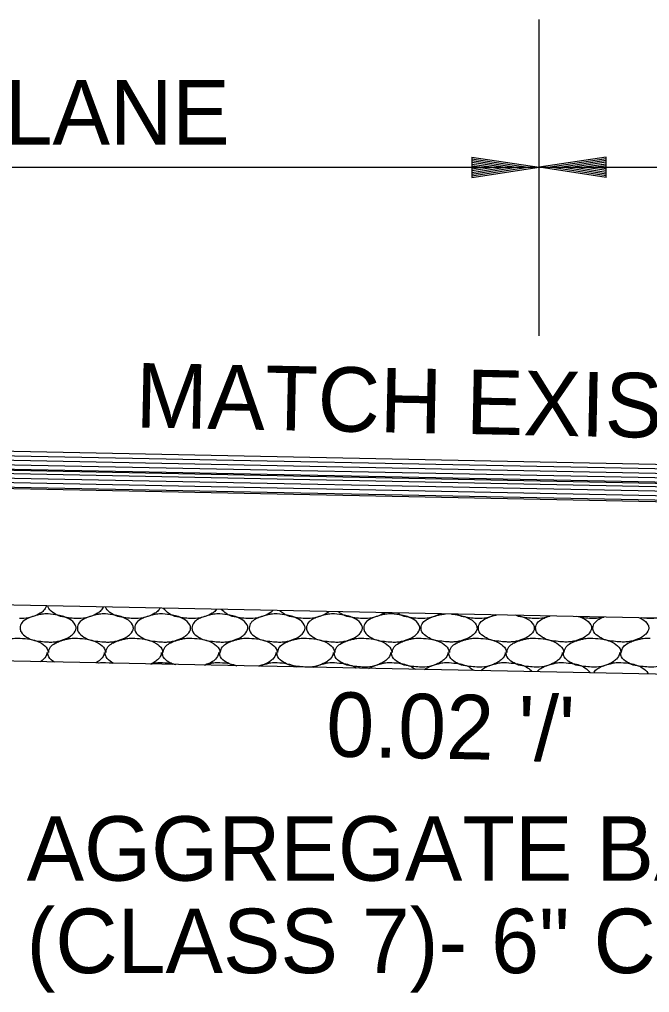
# Model space of a CAD drawing. Extents: x 1364961 to 1365294, y 367927 to 368034.
# Drawn here: x 1365200.85 to 1365206.49, y 367967.68 to 367976.38 of the extents above; entities that cross this region are included whole.
import ezdxf

# ---------------------------------------------------------------- set-up
doc = ezdxf.new("R2010")
doc.units = 0
doc.layers.add('Default', color=7, linetype='Continuous')

msp = doc.modelspace()

# ---------------------------------------------------------------- linework, layer by layer
at = {"layer": 'Default'}
for p, q in [((1365205.4981, 367973.5514), (1365205.4981, 367976.3797)), ((1365204.8981, 367975.1485), (1365205.4981, 367975.0585)), ((1365204.8981, 367975.1485), (1365204.8981, 367974.9685)), ((1365204.8981, 367975.1335), (1365205.3981, 367975.0585)), ((1365204.8981, 367975.1185), (1365205.2951, 367975.0585)), ((1365204.8981, 367975.1035), (1365205.1951, 367975.0585)), ((1365204.8981, 367975.0875), (1365205.0931, 367975.0585)), ((1365204.8981, 367975.0725), (1365204.9931, 367975.0585)), ((1365206.0981, 367975.1485), (1365205.4981, 367975.0585)), ((1365206.0981, 367975.1335), (1365205.5981, 367975.0585)), ((1365206.0981, 367975.1185), (1365205.7011, 367975.0585)), ((1365206.0981, 367975.1035), (1365205.8011, 367975.0585)), ((1365206.0981, 367975.0875), (1365205.9031, 367975.0585)), ((1365206.0981, 367975.0725), (1365206.0031, 367975.0585)), ((1365206.0981, 367974.9685), (1365206.0981, 367975.1485)), ((1365193.4981, 367975.0585), (1365205.4981, 367975.0585)), ((1365204.8981, 367974.9685), (1365205.4981, 367975.0585)), ((1365204.8981, 367975.0295), (1365205.0931, 367975.0585)), ((1365204.8981, 367974.9985), (1365205.2951, 367975.0585)), ((1365204.8981, 367974.9835), (1365205.3981, 367975.0585)), ((1365204.8981, 367975.0135), (1365205.1951, 367975.0585)), ((1365204.8981, 367975.0445), (1365204.9931, 367975.0585)), ((1365205.4981, 367975.0585), (1365217.487, 367975.0585)), ((1365206.0981, 367974.9685), (1365205.4981, 367975.0585)), ((1365206.0981, 367974.9835), (1365205.5981, 367975.0585)), ((1365206.0981, 367974.9985), (1365205.7011, 367975.0585)), ((1365206.0981, 367975.0135), (1365205.8011, 367975.0585)), ((1365206.0981, 367975.0295), (1365205.9031, 367975.0585)), ((1365206.0981, 367975.0445), (1365206.0031, 367975.0585)), ((1365229.476, 367971.9458), (1365193.4981, 367972.6644)), ((1365229.476, 367971.9058), (1365193.4991, 367972.6244)), ((1365229.476, 367971.8657), (1365193.4991, 367972.5844)), ((1365229.476, 367971.7758), (1365193.2513, 367972.4993)), ((1365229.476, 367971.8257), (1365193.5011, 367972.5444)), ((1365229.476, 367971.7857), (1365193.5011, 367972.5044)), ((1365229.476, 367971.7456), (1365193.5021, 367972.4644)), ((1365229.476, 367971.7056), (1365193.5031, 367972.4244)), ((1365229.476, 367971.6656), (1365193.5031, 367972.3844)), ((1365229.476, 367971.6126), (1365193.4981, 367972.3314)), ((1365229.476, 367971.6256), (1365193.5051, 367972.3444)), ((1365217.479, 367970.8114), (1365193.4921, 367971.2914)), ((1365200.8541, 367970.8514), (1365200.8601, 367970.8514)), ((1365201.3661, 367970.8514), (1365201.3721, 367970.8514)), ((1365201.8781, 367970.8514), (1365201.8841, 367970.8514)), ((1365202.3901, 367970.8514), (1365202.3961, 367970.8514)), ((1365202.9021, 367970.8514), (1365202.9081, 367970.8514)), ((1365203.4141, 367970.8514), (1365203.4201, 367970.8514)), ((1365203.9261, 367970.8514), (1365203.9321, 367970.8514)), ((1365204.4381, 367970.8514), (1365204.4441, 367970.8514)), ((1365204.9501, 367970.8514), (1365204.9561, 367970.8514)), ((1365205.4621, 367970.8514), (1365205.4681, 367970.8514)), ((1365205.9741, 367970.8514), (1365205.9801, 367970.8514)), ((1365206.4861, 367970.8514), (1365206.4921, 367970.8514)), ((1365217.479, 367970.3114), (1365193.4821, 367970.7914)), ((1365201.6221, 367970.6334), (1365201.6901, 367970.6274))]:
    msp.add_line(p, q, dxfattribs=at)
for points in [[(1365201.0961, 367971.1394), (1365201.0701, 367971.0974), (1365201.0401, 367971.0734), (1365200.9781, 367971.0454), (1365200.8921, 367971.0274), (1365200.8541, 367971.0274)], [(1365201.3661, 367971.0274), (1365201.3581, 367971.0274), (1365201.2921, 367971.0334), (1365201.2201, 367971.0454), (1365201.1661, 367971.0714), (1365201.1161, 367971.1174), (1365201.1091, 367971.1394)], [(1365201.6041, 367971.1294), (1365201.5821, 367971.0974), (1365201.5521, 367971.0734), (1365201.4901, 367971.0454), (1365201.4041, 367971.0274), (1365201.3661, 367971.0274)], [(1365201.8781, 367971.0274), (1365201.8701, 367971.0274), (1365201.8041, 367971.0334), (1365201.7321, 367971.0454), (1365201.6781, 367971.0714), (1365201.6281, 367971.1174), (1365201.6231, 367971.1284)], [(1365202.1111, 367971.1194), (1365202.0941, 367971.0974), (1365202.0641, 367971.0734), (1365202.0021, 367971.0454), (1365201.9161, 367971.0274), (1365201.8781, 367971.0274)], [(1365202.3901, 367971.0274), (1365202.3821, 367971.0274), (1365202.3161, 367971.0334), (1365202.2441, 367971.0454), (1365202.1901, 367971.0714), (1365202.1401, 367971.1174), (1365202.1391, 367971.1184)], [(1365202.6161, 367971.1084), (1365202.6061, 367971.0974), (1365202.5761, 367971.0734), (1365202.5141, 367971.0454), (1365202.4281, 367971.0274), (1365202.3901, 367971.0274)], [(1365202.9021, 367971.0274), (1365202.8941, 367971.0274), (1365202.8281, 367971.0334), (1365202.7561, 367971.0454), (1365202.7021, 367971.0714), (1365202.6581, 367971.1084)], [(1365203.1191, 367971.0984), (1365203.1181, 367971.0974), (1365203.0881, 367971.0734), (1365203.0261, 367971.0454), (1365202.9401, 367971.0274), (1365202.9021, 367971.0274)], [(1365203.4141, 367971.0274), (1365203.4061, 367971.0274), (1365203.3401, 367971.0334), (1365203.2681, 367971.0454), (1365203.2141, 367971.0714), (1365203.1791, 367971.0974)], [(1365203.6211, 367971.0884), (1365203.6001, 367971.0734), (1365203.5381, 367971.0454), (1365203.4521, 367971.0274), (1365203.4141, 367971.0274)], [(1365203.9261, 367971.0274), (1365203.9181, 367971.0274), (1365203.8521, 367971.0334), (1365203.7801, 367971.0454), (1365203.7261, 367971.0714), (1365203.7031, 367971.0874)], [(1365204.1211, 367971.0784), (1365204.1121, 367971.0734), (1365204.0501, 367971.0454), (1365203.9641, 367971.0274), (1365203.9261, 367971.0274)], [(1365204.4381, 367971.0274), (1365204.4301, 367971.0274), (1365204.3641, 367971.0334), (1365204.2921, 367971.0454), (1365204.2381, 367971.0714), (1365204.2301, 367971.0764)], [(1365201.1101, 367971.0674), (1365201.1981, 367971.0574), (1365201.3001, 367971.0214), (1365201.3521, 367970.9714), (1365201.3601, 367970.9414), (1365201.3321, 367970.8874), (1365201.3021, 367970.8634), (1365201.2401, 367970.8354), (1365201.1541, 367970.8174), (1365201.1101, 367970.8174), (1365201.0441, 367970.8234), (1365200.9721, 367970.8354), (1365200.9181, 367970.8614), (1365200.8681, 367970.9074), (1365200.8601, 367970.9414), (1365200.8761, 367970.9894), (1365200.9161, 367971.0214), (1365200.9561, 367971.0394), (1365201.0161, 367971.0574), (1365201.0541, 367971.0654), (1365201.1101, 367971.0674)], [(1365201.6221, 367971.0674), (1365201.7101, 367971.0574), (1365201.8121, 367971.0214), (1365201.8641, 367970.9714), (1365201.8721, 367970.9414), (1365201.8441, 367970.8874), (1365201.8141, 367970.8634), (1365201.7521, 367970.8354), (1365201.6661, 367970.8174), (1365201.6221, 367970.8174), (1365201.5561, 367970.8234), (1365201.4841, 367970.8354), (1365201.4301, 367970.8614), (1365201.3801, 367970.9074), (1365201.3721, 367970.9414), (1365201.3881, 367970.9894), (1365201.4281, 367971.0214), (1365201.4681, 367971.0394), (1365201.5281, 367971.0574), (1365201.5661, 367971.0654), (1365201.6221, 367971.0674)], [(1365202.1341, 367971.0674), (1365202.2221, 367971.0574), (1365202.3241, 367971.0214), (1365202.3761, 367970.9714), (1365202.3841, 367970.9414), (1365202.3561, 367970.8874), (1365202.3261, 367970.8634), (1365202.2641, 367970.8354), (1365202.1781, 367970.8174), (1365202.1341, 367970.8174), (1365202.0681, 367970.8234), (1365201.9961, 367970.8354), (1365201.9421, 367970.8614), (1365201.8921, 367970.9074), (1365201.8841, 367970.9414), (1365201.9001, 367970.9894), (1365201.9401, 367971.0214), (1365201.9801, 367971.0394), (1365202.0401, 367971.0574), (1365202.0781, 367971.0654), (1365202.1341, 367971.0674)], [(1365202.6461, 367971.0674), (1365202.7341, 367971.0574), (1365202.8361, 367971.0214), (1365202.8881, 367970.9714), (1365202.8961, 367970.9414), (1365202.8681, 367970.8874), (1365202.8381, 367970.8634), (1365202.7761, 367970.8354), (1365202.6901, 367970.8174), (1365202.6461, 367970.8174), (1365202.5801, 367970.8234), (1365202.5081, 367970.8354), (1365202.4541, 367970.8614), (1365202.4041, 367970.9074), (1365202.3961, 367970.9414), (1365202.4121, 367970.9894), (1365202.4521, 367971.0214), (1365202.4921, 367971.0394), (1365202.5521, 367971.0574), (1365202.5901, 367971.0654), (1365202.6461, 367971.0674)], [(1365203.1581, 367971.0674), (1365203.2461, 367971.0574), (1365203.3481, 367971.0214), (1365203.4001, 367970.9714), (1365203.4081, 367970.9414), (1365203.3801, 367970.8874), (1365203.3501, 367970.8634), (1365203.2881, 367970.8354), (1365203.2021, 367970.8174), (1365203.1581, 367970.8174), (1365203.0921, 367970.8234), (1365203.0201, 367970.8354), (1365202.9661, 367970.8614), (1365202.9161, 367970.9074), (1365202.9081, 367970.9414), (1365202.9241, 367970.9894), (1365202.9641, 367971.0214), (1365203.0041, 367971.0394), (1365203.0641, 367971.0574), (1365203.1021, 367971.0654), (1365203.1581, 367971.0674)], [(1365203.6701, 367971.0674), (1365203.7581, 367971.0574), (1365203.8601, 367971.0214), (1365203.9121, 367970.9714), (1365203.9201, 367970.9414), (1365203.8921, 367970.8874), (1365203.8621, 367970.8634), (1365203.8001, 367970.8354), (1365203.7141, 367970.8174), (1365203.6701, 367970.8174), (1365203.6041, 367970.8234), (1365203.5321, 367970.8354), (1365203.4781, 367970.8614), (1365203.4281, 367970.9074), (1365203.4201, 367970.9414), (1365203.4361, 367970.9894), (1365203.4761, 367971.0214), (1365203.5161, 367971.0394), (1365203.5761, 367971.0574), (1365203.6141, 367971.0654), (1365203.6701, 367971.0674)], [(1365204.1821, 367971.0674), (1365204.2701, 367971.0574), (1365204.3721, 367971.0214), (1365204.4241, 367970.9714), (1365204.4321, 367970.9414), (1365204.4041, 367970.8874), (1365204.3741, 367970.8634), (1365204.3121, 367970.8354), (1365204.2261, 367970.8174), (1365204.1821, 367970.8174), (1365204.1161, 367970.8234), (1365204.0441, 367970.8354), (1365203.9901, 367970.8614), (1365203.9401, 367970.9074), (1365203.9321, 367970.9414), (1365203.9481, 367970.9894), (1365203.9881, 367971.0214), (1365204.0281, 367971.0394), (1365204.0881, 367971.0574), (1365204.1261, 367971.0654), (1365204.1821, 367971.0674)], [(1365204.6161, 367971.0684), (1365204.5621, 367971.0454), (1365204.4761, 367971.0274), (1365204.4381, 367971.0274)], [(1365204.7171, 367971.0664), (1365204.7821, 367971.0574), (1365204.8841, 367971.0214), (1365204.9361, 367970.9714), (1365204.9441, 367970.9414), (1365204.9161, 367970.8874), (1365204.8861, 367970.8634), (1365204.8241, 367970.8354), (1365204.7381, 367970.8174), (1365204.6941, 367970.8174), (1365204.6281, 367970.8234), (1365204.5561, 367970.8354), (1365204.5021, 367970.8614), (1365204.4521, 367970.9074), (1365204.4441, 367970.9414), (1365204.4601, 367970.9894), (1365204.5001, 367971.0214), (1365204.5401, 367971.0394), (1365204.6001, 367971.0574), (1365204.6381, 367971.0654), (1365204.6621, 367971.0674)], [(1365204.9501, 367971.0274), (1365204.9421, 367971.0274), (1365204.8761, 367971.0334), (1365204.8041, 367971.0454), (1365204.7591, 367971.0664)], [(1365205.1081, 367971.0594), (1365205.0741, 367971.0454), (1365204.9881, 367971.0274), (1365204.9501, 367971.0274)], [(1365205.3051, 367971.0554), (1365205.3961, 367971.0214), (1365205.4481, 367970.9714), (1365205.4561, 367970.9414), (1365205.4281, 367970.8874), (1365205.3981, 367970.8634), (1365205.3361, 367970.8354), (1365205.2501, 367970.8174), (1365205.2061, 367970.8174), (1365205.1401, 367970.8234), (1365205.0681, 367970.8354), (1365205.0141, 367970.8614), (1365204.9641, 367970.9074), (1365204.9561, 367970.9414), (1365204.9721, 367970.9894), (1365205.0121, 367971.0214), (1365205.0521, 367971.0394), (1365205.1121, 367971.0574), (1365205.1171, 367971.0584)], [(1365205.4621, 367971.0274), (1365205.4541, 367971.0274), (1365205.3881, 367971.0334), (1365205.3161, 367971.0454), (1365205.2901, 367971.0554)], [(1365205.5971, 367971.0494), (1365205.5861, 367971.0454), (1365205.5001, 367971.0274), (1365205.4621, 367971.0274)], [(1365205.8561, 367971.0444), (1365205.9081, 367971.0214), (1365205.9601, 367970.9714), (1365205.9681, 367970.9414), (1365205.9401, 367970.8874), (1365205.9101, 367970.8634), (1365205.8481, 367970.8354), (1365205.7621, 367970.8174), (1365205.7181, 367970.8174), (1365205.6521, 367970.8234), (1365205.5801, 367970.8354), (1365205.5261, 367970.8614), (1365205.4761, 367970.9074), (1365205.4681, 367970.9414), (1365205.4841, 367970.9894), (1365205.5241, 367971.0214), (1365205.5641, 367971.0394), (1365205.5951, 367971.0494)], [(1365205.9741, 367971.0274), (1365205.9661, 367971.0274), (1365205.9001, 367971.0334), (1365205.8321, 367971.0444)], [(1365206.0791, 367971.0394), (1365206.0121, 367971.0274), (1365205.9741, 367971.0274)], [(1365206.3961, 367971.0334), (1365206.4201, 367971.0214), (1365206.4721, 367970.9714), (1365206.4801, 367970.9414), (1365206.4521, 367970.8874), (1365206.4221, 367970.8634), (1365206.3601, 367970.8354), (1365206.2741, 367970.8174), (1365206.2301, 367970.8174), (1365206.1641, 367970.8234), (1365206.0921, 367970.8354), (1365206.0381, 367970.8614), (1365205.9881, 367970.9074), (1365205.9801, 367970.9414), (1365205.9961, 367970.9894), (1365206.0361, 367971.0214), (1365206.0761, 367971.0394), (1365206.0771, 367971.0394)], [(1365206.4861, 367971.0274), (1365206.4781, 367971.0274), (1365206.4181, 367971.0324)], [(1365206.5501, 367971.0304), (1365206.5241, 367971.0274), (1365206.4861, 367971.0274)], [(1365200.6041, 367970.7234), (1365200.6041, 367970.7254), (1365200.6201, 367970.7734), (1365200.6601, 367970.8054), (1365200.7001, 367970.8234), (1365200.7601, 367970.8414), (1365200.7981, 367970.8494), (1365200.8541, 367970.8514)], [(1365200.8601, 367970.8514), (1365200.9481, 367970.8414), (1365201.0501, 367970.8054), (1365201.1021, 367970.7554), (1365201.1101, 367970.7254), (1365201.1101, 367970.7234)], [(1365201.1161, 367970.7234), (1365201.1161, 367970.7254), (1365201.1321, 367970.7734), (1365201.1721, 367970.8054), (1365201.2121, 367970.8234), (1365201.2721, 367970.8414), (1365201.3101, 367970.8494), (1365201.3661, 367970.8514)], [(1365201.3721, 367970.8514), (1365201.4601, 367970.8414), (1365201.5621, 367970.8054), (1365201.6141, 367970.7554), (1365201.6221, 367970.7254), (1365201.6221, 367970.7234)], [(1365201.6281, 367970.7234), (1365201.6281, 367970.7254), (1365201.6441, 367970.7734), (1365201.6841, 367970.8054), (1365201.7241, 367970.8234), (1365201.7841, 367970.8414), (1365201.8221, 367970.8494), (1365201.8781, 367970.8514)], [(1365201.8841, 367970.8514), (1365201.9721, 367970.8414), (1365202.0741, 367970.8054), (1365202.1261, 367970.7554), (1365202.1341, 367970.7254), (1365202.1341, 367970.7234)], [(1365202.1401, 367970.7234), (1365202.1401, 367970.7254), (1365202.1561, 367970.7734), (1365202.1961, 367970.8054), (1365202.2361, 367970.8234), (1365202.2961, 367970.8414), (1365202.3341, 367970.8494), (1365202.3901, 367970.8514)], [(1365202.3961, 367970.8514), (1365202.4841, 367970.8414), (1365202.5861, 367970.8054), (1365202.6381, 367970.7554), (1365202.6461, 367970.7254), (1365202.6461, 367970.7234)], [(1365202.6521, 367970.7234), (1365202.6521, 367970.7254), (1365202.6681, 367970.7734), (1365202.7081, 367970.8054), (1365202.7481, 367970.8234), (1365202.8081, 367970.8414), (1365202.8461, 367970.8494), (1365202.9021, 367970.8514)], [(1365202.9081, 367970.8514), (1365202.9961, 367970.8414), (1365203.0981, 367970.8054), (1365203.1501, 367970.7554), (1365203.1581, 367970.7254), (1365203.1581, 367970.7234)], [(1365203.1641, 367970.7234), (1365203.1641, 367970.7254), (1365203.1801, 367970.7734), (1365203.2201, 367970.8054), (1365203.2601, 367970.8234), (1365203.3201, 367970.8414), (1365203.3581, 367970.8494), (1365203.4141, 367970.8514)], [(1365203.4201, 367970.8514), (1365203.5081, 367970.8414), (1365203.6101, 367970.8054), (1365203.6621, 367970.7554), (1365203.6701, 367970.7254), (1365203.6701, 367970.7234)], [(1365203.6761, 367970.7234), (1365203.6761, 367970.7254), (1365203.6921, 367970.7734), (1365203.7321, 367970.8054), (1365203.7721, 367970.8234), (1365203.8321, 367970.8414), (1365203.8701, 367970.8494), (1365203.9261, 367970.8514)], [(1365203.9321, 367970.8514), (1365204.0201, 367970.8414), (1365204.1221, 367970.8054), (1365204.1741, 367970.7554), (1365204.1821, 367970.7254), (1365204.1821, 367970.7234)], [(1365204.1881, 367970.7234), (1365204.1881, 367970.7254), (1365204.2041, 367970.7734), (1365204.2441, 367970.8054), (1365204.2841, 367970.8234), (1365204.3441, 367970.8414), (1365204.3821, 367970.8494), (1365204.4381, 367970.8514)], [(1365204.4441, 367970.8514), (1365204.5321, 367970.8414), (1365204.6341, 367970.8054), (1365204.6861, 367970.7554), (1365204.6941, 367970.7254), (1365204.6941, 367970.7234)], [(1365204.7001, 367970.7234), (1365204.7001, 367970.7254), (1365204.7161, 367970.7734), (1365204.7561, 367970.8054), (1365204.7961, 367970.8234), (1365204.8561, 367970.8414), (1365204.8941, 367970.8494), (1365204.9501, 367970.8514)], [(1365204.9561, 367970.8514), (1365205.0441, 367970.8414), (1365205.1461, 367970.8054), (1365205.1981, 367970.7554), (1365205.2061, 367970.7254), (1365205.2061, 367970.7234)], [(1365205.2121, 367970.7234), (1365205.2121, 367970.7254), (1365205.2281, 367970.7734), (1365205.2681, 367970.8054), (1365205.3081, 367970.8234), (1365205.3681, 367970.8414), (1365205.4061, 367970.8494), (1365205.4621, 367970.8514)], [(1365205.4681, 367970.8514), (1365205.5561, 367970.8414), (1365205.6581, 367970.8054), (1365205.7101, 367970.7554), (1365205.7181, 367970.7254), (1365205.7181, 367970.7234)], [(1365205.7241, 367970.7234), (1365205.7241, 367970.7254), (1365205.7401, 367970.7734), (1365205.7801, 367970.8054), (1365205.8201, 367970.8234), (1365205.8801, 367970.8414), (1365205.9181, 367970.8494), (1365205.9741, 367970.8514)], [(1365205.9801, 367970.8514), (1365206.0681, 367970.8414), (1365206.1701, 367970.8054), (1365206.2221, 367970.7554), (1365206.2301, 367970.7254), (1365206.2301, 367970.7234)], [(1365206.2361, 367970.7234), (1365206.2361, 367970.7254), (1365206.2521, 367970.7734), (1365206.2921, 367970.8054), (1365206.3321, 367970.8234), (1365206.3921, 367970.8414), (1365206.4301, 367970.8494), (1365206.4861, 367970.8514)], [(1365201.0981, 367970.7234), (1365201.0981, 367970.7174), (1365201.0701, 367970.6634), (1365201.0411, 367970.6404)], [(1365201.1661, 367970.6374), (1365201.1161, 367970.6834), (1365201.1081, 367970.7174), (1365201.1081, 367970.7234)], [(1365201.6101, 367970.7234), (1365201.6101, 367970.7174), (1365201.5821, 367970.6634), (1365201.5521, 367970.6394), (1365201.5351, 367970.6304)], [(1365201.6951, 367970.6274), (1365201.6781, 367970.6374), (1365201.6281, 367970.6834), (1365201.6201, 367970.7174), (1365201.6201, 367970.7234)], [(1365202.1221, 367970.7234), (1365202.1221, 367970.7174), (1365202.0941, 367970.6634), (1365202.0641, 367970.6394), (1365202.0261, 367970.6204)], [(1365202.2281, 367970.6164), (1365202.1901, 367970.6374), (1365202.1401, 367970.6834), (1365202.1321, 367970.7174), (1365202.1321, 367970.7234)], [(1365202.6341, 367970.7234), (1365202.6341, 367970.7174), (1365202.6061, 367970.6634), (1365202.5761, 367970.6394), (1365202.5141, 367970.6114), (1365202.5121, 367970.6104)], [(1365202.7861, 367970.6054), (1365202.7561, 367970.6114), (1365202.7021, 367970.6374), (1365202.6521, 367970.6834), (1365202.6441, 367970.7174), (1365202.6441, 367970.7234)], [(1365203.1461, 367970.7234), (1365203.1461, 367970.7174), (1365203.1181, 367970.6634), (1365203.0881, 367970.6394), (1365203.0261, 367970.6114), (1365202.9911, 367970.6014)], [(1365203.4141, 367970.5934), (1365203.4061, 367970.5934), (1365203.3401, 367970.5994), (1365203.2681, 367970.6114), (1365203.2141, 367970.6374), (1365203.1641, 367970.6834), (1365203.1561, 367970.7174), (1365203.1561, 367970.7234)], [(1365203.6581, 367970.7234), (1365203.6581, 367970.7174), (1365203.6301, 367970.6634), (1365203.6001, 367970.6394), (1365203.5381, 367970.6114), (1365203.4521, 367970.5934), (1365203.4141, 367970.5934)], [(1365203.9261, 367970.5934), (1365203.9181, 367970.5934), (1365203.8521, 367970.5994), (1365203.7801, 367970.6114), (1365203.7261, 367970.6374), (1365203.6761, 367970.6834), (1365203.6681, 367970.7174), (1365203.6681, 367970.7234)], [(1365204.1701, 367970.7234), (1365204.1701, 367970.7174), (1365204.1421, 367970.6634), (1365204.1121, 367970.6394), (1365204.0501, 367970.6114), (1365203.9641, 367970.5934), (1365203.9261, 367970.5934)], [(1365204.4381, 367970.5934), (1365204.4301, 367970.5934), (1365204.3641, 367970.5994), (1365204.2921, 367970.6114), (1365204.2381, 367970.6374), (1365204.1881, 367970.6834), (1365204.1801, 367970.7174), (1365204.1801, 367970.7234)], [(1365204.6821, 367970.7234), (1365204.6821, 367970.7174), (1365204.6541, 367970.6634), (1365204.6241, 367970.6394), (1365204.5621, 367970.6114), (1365204.4761, 367970.5934), (1365204.4381, 367970.5934)], [(1365204.9501, 367970.5934), (1365204.9421, 367970.5934), (1365204.8761, 367970.5994), (1365204.8041, 367970.6114), (1365204.7501, 367970.6374), (1365204.7001, 367970.6834), (1365204.6921, 367970.7174), (1365204.6921, 367970.7234)], [(1365205.1941, 367970.7234), (1365205.1941, 367970.7174), (1365205.1661, 367970.6634), (1365205.1361, 367970.6394), (1365205.0741, 367970.6114), (1365204.9881, 367970.5934), (1365204.9501, 367970.5934)], [(1365205.4621, 367970.5934), (1365205.4541, 367970.5934), (1365205.3881, 367970.5994), (1365205.3161, 367970.6114), (1365205.2621, 367970.6374), (1365205.2121, 367970.6834), (1365205.2041, 367970.7174), (1365205.2041, 367970.7234)], [(1365205.7061, 367970.7234), (1365205.7061, 367970.7174), (1365205.6781, 367970.6634), (1365205.6481, 367970.6394), (1365205.5861, 367970.6114), (1365205.5001, 367970.5934), (1365205.4621, 367970.5934)], [(1365205.9741, 367970.5934), (1365205.9661, 367970.5934), (1365205.9001, 367970.5994), (1365205.8281, 367970.6114), (1365205.7741, 367970.6374), (1365205.7241, 367970.6834), (1365205.7161, 367970.7174), (1365205.7161, 367970.7234)], [(1365206.2181, 367970.7234), (1365206.2181, 367970.7174), (1365206.1901, 367970.6634), (1365206.1601, 367970.6394), (1365206.0981, 367970.6114), (1365206.0121, 367970.5934), (1365205.9741, 367970.5934)], [(1365206.4861, 367970.5934), (1365206.4781, 367970.5934), (1365206.4121, 367970.5994), (1365206.3401, 367970.6114), (1365206.2861, 367970.6374), (1365206.2361, 367970.6834), (1365206.2281, 367970.7174), (1365206.2281, 367970.7234)], [(1365206.7301, 367970.7234), (1365206.7301, 367970.7174), (1365206.7021, 367970.6634), (1365206.6721, 367970.6394), (1365206.6101, 367970.6114), (1365206.5241, 367970.5934), (1365206.4861, 367970.5934)], [(1365201.5571, 367970.6294), (1365201.5661, 367970.6314), (1365201.6221, 367970.6334)], [(1365202.0291, 367970.6204), (1365202.0401, 367970.6234), (1365202.0781, 367970.6314), (1365202.1341, 367970.6334)], [(1365202.1341, 367970.6334), (1365202.2221, 367970.6234), (1365202.2531, 367970.6164)], [(1365202.5091, 367970.6104), (1365202.5521, 367970.6234), (1365202.5901, 367970.6314), (1365202.6461, 367970.6334)], [(1365202.6461, 367970.6334), (1365202.7341, 367970.6234), (1365202.7981, 367970.6054)], [(1365202.9931, 367970.6014), (1365203.0041, 367970.6054), (1365203.0641, 367970.6234), (1365203.1021, 367970.6314), (1365203.1581, 367970.6334)], [(1365203.1581, 367970.6334), (1365203.2461, 367970.6234), (1365203.3341, 367970.5944)], [(1365203.4841, 367970.5914), (1365203.5161, 367970.6054), (1365203.5761, 367970.6234), (1365203.6141, 367970.6314), (1365203.6701, 367970.6334)], [(1365203.6701, 367970.6334), (1365203.7581, 367970.6234), (1365203.8601, 367970.5874), (1365203.8661, 367970.5834)], [(1365203.9771, 367970.5814), (1365203.9881, 367970.5874), (1365204.0281, 367970.6054), (1365204.0881, 367970.6234), (1365204.1261, 367970.6314), (1365204.1821, 367970.6334)], [(1365204.1821, 367970.6334), (1365204.2701, 367970.6234), (1365204.3721, 367970.5874), (1365204.3931, 367970.5734)], [(1365204.4751, 367970.5714), (1365204.5001, 367970.5874), (1365204.5401, 367970.6054), (1365204.6001, 367970.6234), (1365204.6381, 367970.6314), (1365204.6941, 367970.6334)], [(1365204.6941, 367970.6334), (1365204.7821, 367970.6234), (1365204.8841, 367970.5874), (1365204.9161, 367970.5624)], [(1365204.9771, 367970.5614), (1365205.0121, 367970.5874), (1365205.0521, 367970.6054), (1365205.1121, 367970.6234), (1365205.1501, 367970.6314), (1365205.2061, 367970.6334)], [(1365205.2061, 367970.6334), (1365205.2941, 367970.6234), (1365205.3961, 367970.5874), (1365205.4371, 367970.5524)], [(1365205.4811, 367970.5514), (1365205.4841, 367970.5554), (1365205.5241, 367970.5874), (1365205.5641, 367970.6054), (1365205.6241, 367970.6234), (1365205.6621, 367970.6314), (1365205.7181, 367970.6334)], [(1365205.7181, 367970.6334), (1365205.8061, 367970.6234), (1365205.9081, 367970.5874), (1365205.9571, 367970.5414)], [(1365205.9881, 367970.5414), (1365205.9961, 367970.5554), (1365206.0361, 367970.5874), (1365206.0761, 367970.6054), (1365206.1361, 367970.6234), (1365206.1741, 367970.6314), (1365206.2301, 367970.6334)], [(1365206.2301, 367970.6334), (1365206.3181, 367970.6234), (1365206.4201, 367970.5874), (1365206.4721, 367970.5374), (1365206.4751, 367970.5314)]]:
    msp.add_spline(points, degree=3, dxfattribs=at)

# ---------------------------------------------------------------- texts
for s, p in [('12\'-0" TRAFFIC LANE', (1365195.0792, 367975.2615)), ('AGGREGATE BASE COURSE', (1365200.9181, 367968.6842)), ('(CLASS 7)- 6" COMP\'D. DEPTH', (1365200.9181, 367967.8582))]:
    msp.add_text(s, height=0.576, dxfattribs=at).set_placement(p)
for s, p in [('MATCH EXISTING', (1365201.8891, 367972.735)), ("0.02 '/'", (1365203.5918, 367969.7949))]:
    msp.add_text(s, height=0.576, rotation=358.85371, dxfattribs=at).set_placement(p)

doc.saveas('drawing.dxf')
